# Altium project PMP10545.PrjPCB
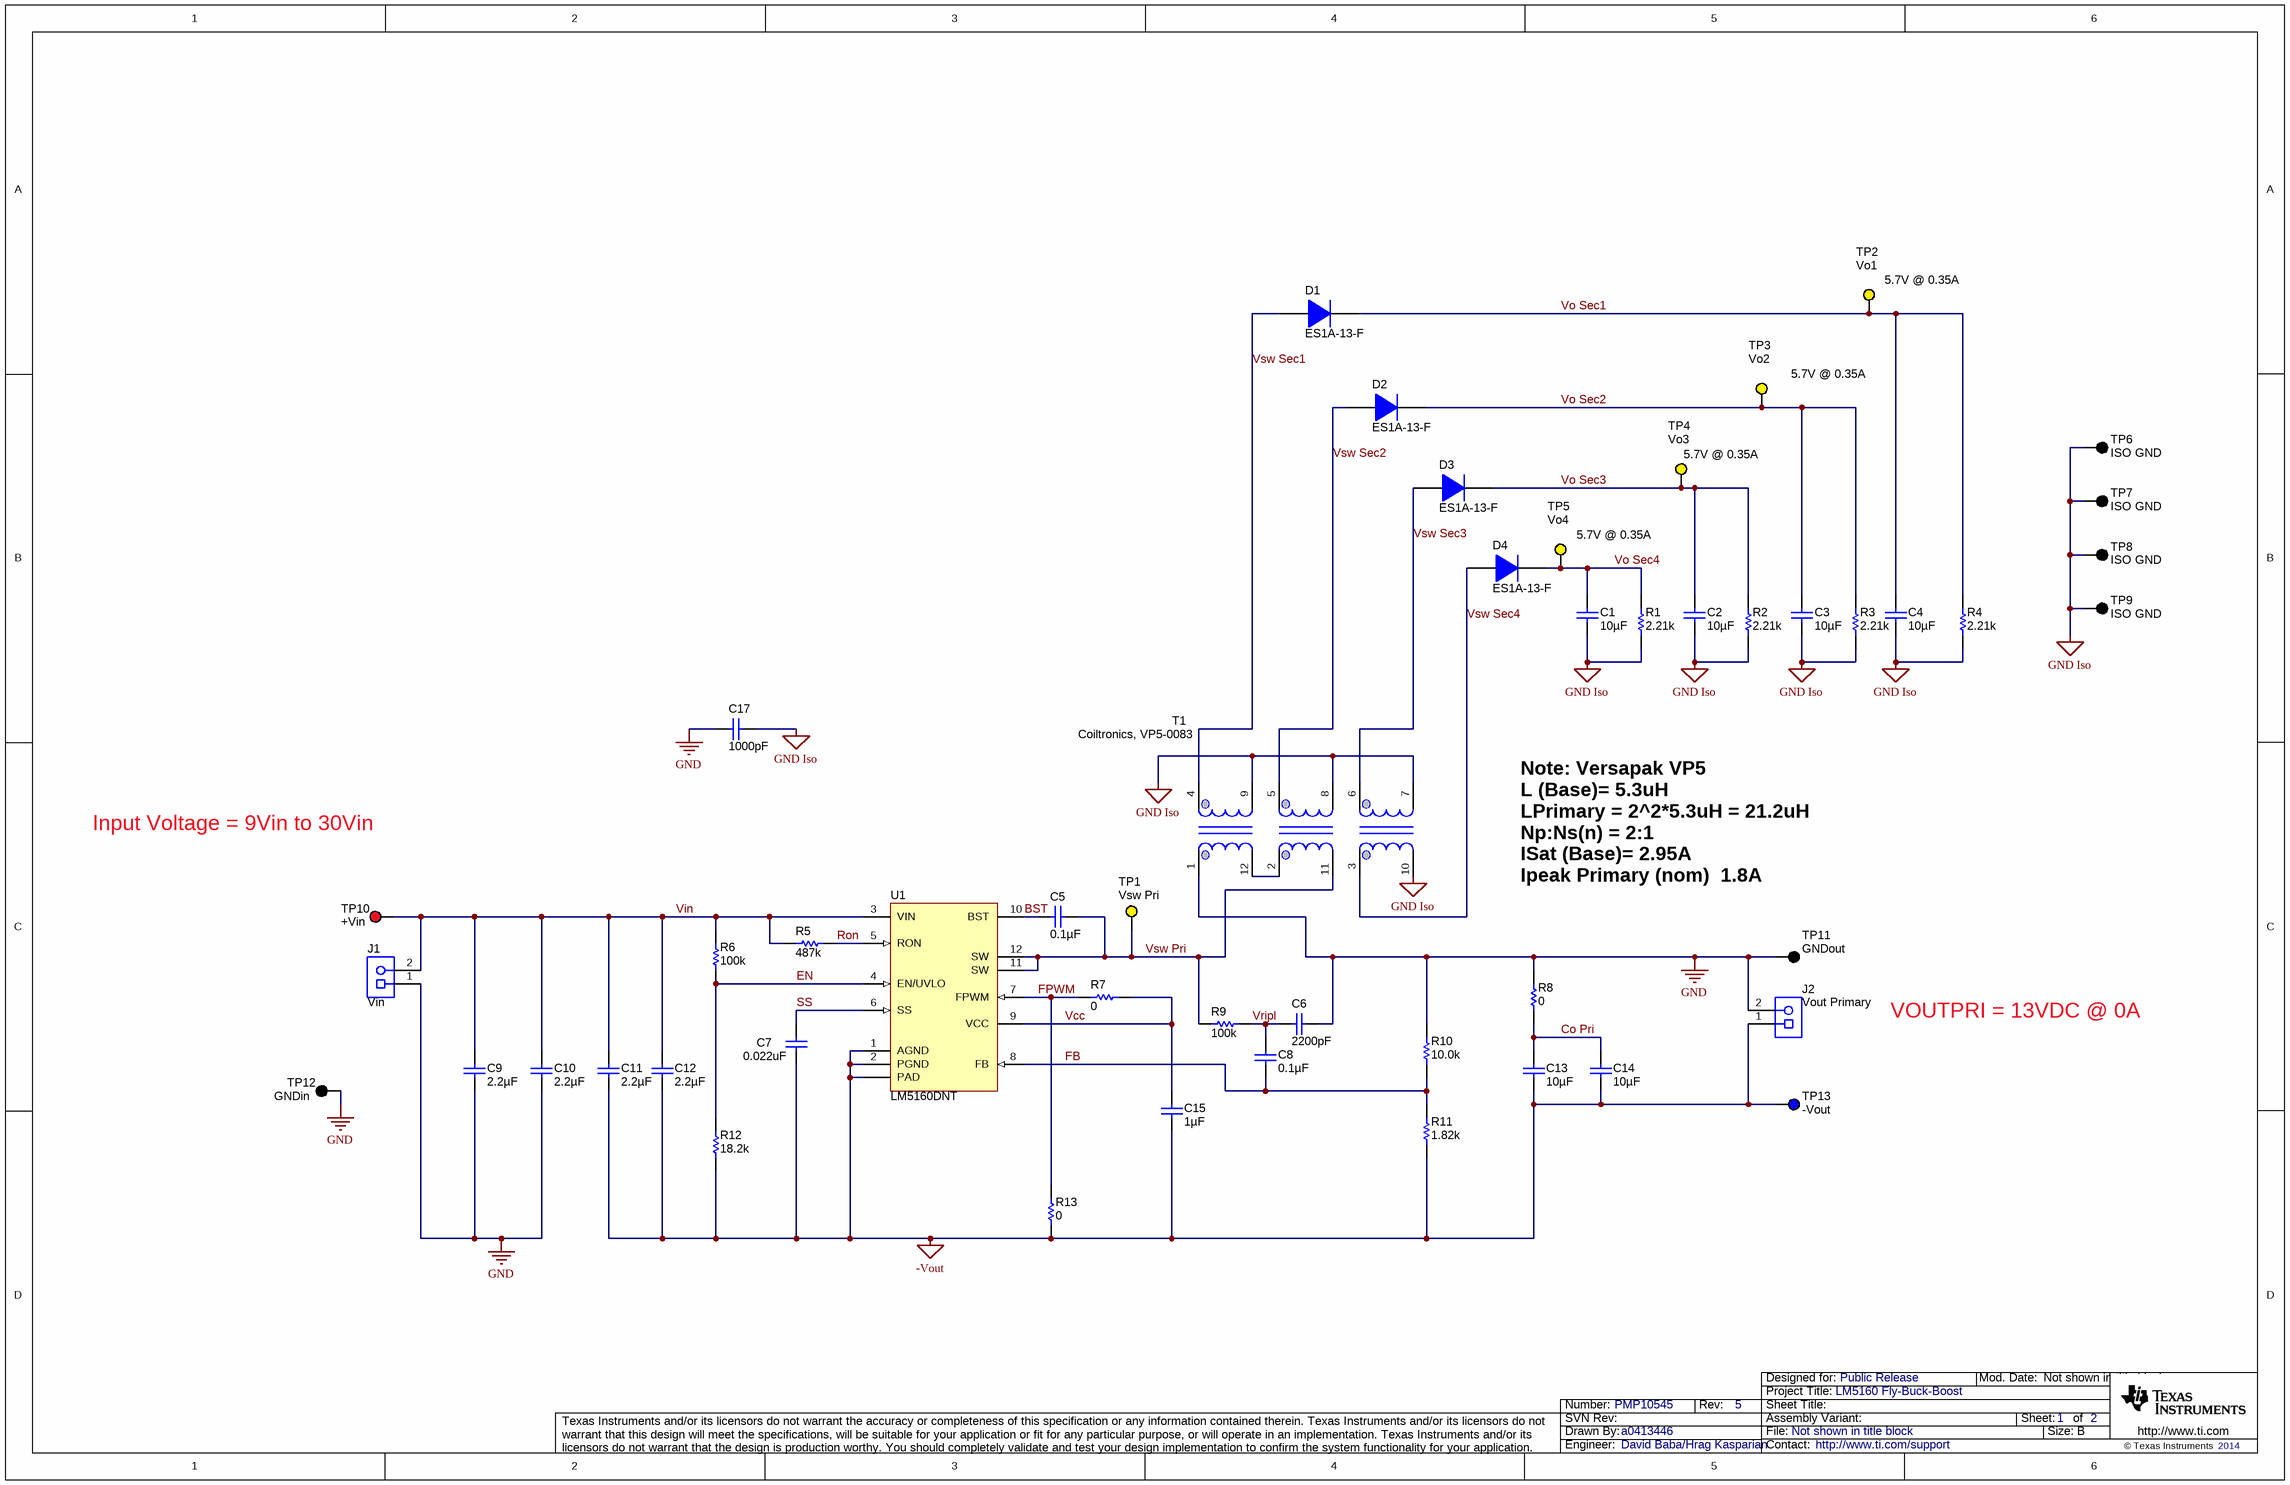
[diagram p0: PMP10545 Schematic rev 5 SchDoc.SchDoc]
TID: PMP10545; TechSupport: http://www.ti.com/support; SCH_Rev: 5; PRJ_Title: LM5160 Fly-Buck-Boost; PRJ_Number: PMP10545; PRJ_Engineer: David Baba/Hrag Kasparian; PRJ_Customer: Public Release; PCB_Layout: Hrag Kasparian; CopyrightYear: 2014
2 sheets, 63 parts. Net scope: global (net labels, ports and power ports of the same name join across sheets).
Board file: PMP10545.PcbDoc
Sheets:
  PMP10545 Schematic rev 5 SchDoc.SchDoc
  PMP10545_Hardware_ANSI-B.SchDoc

## Sheet PMP10545 Schematic rev 5 SchDoc.SchDoc
size 431 x 279 mm; Date: Not shown in title block; ApprovedBy: Not shown in title block; CheckedBy: Not shown in title block; Author: Not shown in title block; CompanyName: Not shown in title block; DrawnBy: a0413446; Engineer: Not shown in title block; Organization: Not shown in title block; Address1: Not shown in title block; Address2: Not shown in title block; Address3: Not shown in title block; Address4: Not shown in title block; DocumentNumber: 1; Revision: Use project parameter SCH_Rev; SheetNumber: 1; SheetTotal: 2; PageSetup: Record=PageOptions¦CenterHorizontal=True¦CenterVertical=True¦PrintScale=0.61¦XCorrection=1.00¦YCorrection=1.00¦PrintKind=0¦BorderSize=5000000¦LeftOffset=0¦BottomOffset=0¦Orientation=2¦PaperLength=1000¦PaperWidth=1000¦Scale=100¦PaperSource=15¦PrintQuality=600¦MediaType=1¦DitherType=10¦PaperKind=Letter¦PrintScaleMode=1

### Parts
C1  ValueDisplayed: 10µF  [0805_HV]  (hidden comment: EMK212BJ106KG-T)
C2  ValueDisplayed: 10µF  [0805_HV]  (hidden comment: EMK212BJ106KG-T)
C3  ValueDisplayed: 10µF  [0805_HV]  (hidden comment: EMK212BJ106KG-T)
C4  ValueDisplayed: 10µF  [0805_HV]  (hidden comment: EMK212BJ106KG-T)
C5  ValueDisplayed: 0.1µF  [0603]  (hidden comment: C0603C104J3RAC)
C6  ValueDisplayed: 2200pF  [0603]  (hidden comment: C0603C222K5RAC)
C7  ValueDisplayed: 0.022uF  [0603]  (hidden comment: GRM188R71C223KA01D)
C8  ValueDisplayed: 0.1µF  [0603]  (hidden comment: C0603C104J3RAC)
C9  ValueDisplayed: 2.2µF  [1206]  (hidden comment: GRM31CR61H225KA88L)
C10  ValueDisplayed: 2.2µF  [1206]  (hidden comment: GRM31CR61H225KA88L)
C11  ValueDisplayed: 2.2µF  [1206]  (hidden comment: GRM31CR61H225KA88L)
C12  ValueDisplayed: 2.2µF  [1206]  (hidden comment: GRM31CR61H225KA88L)
C13  ValueDisplayed: 10µF  [0805_HV]  (hidden comment: EMK212BJ106KG-T)
C14  ValueDisplayed: 10µF  [0805_HV]  (hidden comment: EMK212BJ106KG-T)
C15  ValueDisplayed: 1µF  [0603]  (hidden comment: GRM188R71E105KA12D)
C17  ValueDisplayed: 1000pF  [1206]  (hidden comment: VJ1206A102JXGAT5Z)
D1  ES1A-13-F  [SMA]
D2  ES1A-13-F  [SMA]
D3  ES1A-13-F  [SMA]
D4  ES1A-13-F  [SMA]
J1  Vin  [PhoenixConact_1727010]
J2  Vout Primary  [PhoenixConact_1727010]
R1  ValueDisplayed: 2.21k  [0603]  (hidden comment: CRCW06032K21FKEA)
R2  ValueDisplayed: 2.21k  [0603]  (hidden comment: CRCW06032K21FKEA)
R3  ValueDisplayed: 2.21k  [0603]  (hidden comment: CRCW06032K21FKEA)
R4  ValueDisplayed: 2.21k  [0603]  (hidden comment: CRCW06032K21FKEA)
R5  value 487k  [0603]  (hidden comment: CRCW0603487KFKEA)
R6  ValueDisplayed: 100k  [0603]  (hidden comment: CRCW0603100KFKEA)
R7  ValueDisplayed: 0  [0603]  (hidden comment: CRCW06030000Z0EA)
R8  ValueDisplayed: 0  [0805_HV]  (hidden comment: CRCW08050000Z0EA)
R9  value 100k  [0603]  (hidden comment: CRCW0603100KFKEA)
R10  value 10.0k  [0603]  (hidden comment: CRCW060310K0FKEA)
R11  ValueDisplayed: 1.82k  [0603]  (hidden comment: CRCW06031K82FKEA)
R12  value 18.2k  [0603]  (hidden comment: CRCW060318K2FKEA)
R13  ValueDisplayed: 0  [0603]  (hidden comment: CRCW06030000Z0EA)
T1  Coiltronics, VP5-0083  [VP5]
TP1  Vsw Pri  [Keystone5014]
TP2  Vo1  [Keystone5014]
TP3  Vo2  [Keystone5014]
TP4  Vo3  [Keystone5014]
TP5  Vo4  [Keystone5014]
TP6  ISO GND  [Keystone5011]
TP7  ISO GND  [Keystone5011]
TP8  ISO GND  [Keystone5011]
TP9  ISO GND  [Keystone5011]
TP10  +Vin  [Keystone5010]
TP11  GNDout  [Keystone5011]
TP12  GNDin  [Keystone5011]
TP13  -Vout  [Keystone5127]
U1  LM5160DNT  [DNT0012B]

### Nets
-Vout: C7.2 C11.2 C12.2 C13.2 C14.2 C15.2 J2.1 R11.1 R12.1 R13.1 TP13.1 U1.1(AGND) U1.2(PGND) U1.13(PAD)
GND: C6.2 C9.2 C10.2 C17.2 J1.1 J2.2 R8.2 R10.2 T1.1 TP11.1 TP12.1
GND Iso: C1.2 C2.2 C3.2 C4.2 C17.1 R1.1 R2.1 R3.1 R4.1 T1.7 T1.8 T1.9 T1.10 TP6.1 TP7.1 TP8.1 TP9.1
BST: C5.2 U1.10(BST)
Co Pri: C13.1 C14.1 R8.1
EN: R6.1 R12.2 U1.4(EN/UVLO)
FB: C8.2 R10.1 R11.2 U1.8(FB)
FPWM: R7.2 R13.2 U1.7(FPWM)
Ron: R5.1 U1.5(RON)
SS: C7.1 U1.6(SS)
Vcc: C15.1 R7.1 U1.9(VCC)
Vin: C9.1 C10.1 C11.1 C12.1 J1.2 R5.2 R6.2 TP10.1 U1.3(VIN)
Vo Sec1: C4.1 D1.1(K) R4.2 TP2.1
Vo Sec2: C3.1 D2.1(K) R3.2 TP3.1
Vo Sec3: C2.1 D3.1(K) R2.2 TP4.1
Vo Sec4: C1.1 D4.1(K) R1.2 TP5.1
Vripl: C6.1 C8.1 R9.2
Vsw Pri: C5.1 R9.1 T1.11 TP1.1 U1.11(SW) U1.12(SW)
Vsw Sec1: D1.2(A) T1.4
Vsw Sec2: D2.2(A) T1.5
Vsw Sec3: D3.2(A) T1.6
Vsw Sec4: D4.2(A) T1.3
NetT1_2: T1.2 T1.12

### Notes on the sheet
- (near TP2) 5.7V @ 0.35A
- (near TP3) 5.7V @ 0.35A
- (near TP4) 5.7V @ 0.35A
- (near TP5) 5.7V @ 0.35A
- Input Voltage = 9Vin to 30Vin
- Note: Versapak VP5
  L (Base)= 5.3uH
  LPrimary = 2^2*5.3uH = 21.2uH
  Np:Ns(n) = 2:1
  ISat (Base)= 2.95A
  Ipeak Primary (nom)  1.8A
- VOUTPRI = 13VDC @ 0A

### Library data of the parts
C1-C4 C13 C14 = EMK212BJ106KG-T: CAP, CERM, 10uF, 16V, +/-10%, X5R, 0805; Manufacturer: Taiyo Yuden; Polarized: N; CompType: Capacitor; U/M: EA; Cap_F: 0.00001; Tolerance_%: 10; Value1: Unknown; VDC_V: 16; TaMin_C: -55; TaMax_C: 85; Cap_Case: 0805
C5 C8 = C0603C104J3RAC: CAP, CERM, 0.1uF, 25V, +/-5%, X7R, 0603; Manufacturer: Kemet; Polarized: N; CompType: Capacitor; U/M: EA; Cap_F: 0.0000001; Tolerance_%: 5; Value1: Unknown; VDC_V: 25; TaMin_C: -55; TaMax_C: 125
C6 = C0603C222K5RAC: CAP, CERM, 2200pF, 50V, +/-10%, X7R, 0603; Manufacturer: Kemet; Polarized: N; CompType: Capacitor; U/M: EA; Cap_F: 0.0000000022; Tolerance_%: 10; Value1: Unknown; VDC_V: 50; TaMin_C: -55; TaMax_C: 125
C7 = GRM188R71C223KA01D: CAP, CERM, 0.022uF, 16V, +/-10%, X7R, 0603; Manufacturer: MuRata; Polarized: N; CompType: Capacitor; U/M: EA; Cap_F: 0.000000022; Tolerance_%: 10; Value1: Unknown; VDC_V: 16; TaMin_C: -55; TaMax_C: 125
C9-C12 = GRM31CR61H225KA88L: CAP, CERM, 2.2uF, 50V, +/-10%, X5R, 1206; Manufacturer: MuRata; Polarized: N; CompType: Capacitor; U/M: EA; Cap_F: 0.0000022; Tolerance_%: 10; Value1: Unknown; VDC_V: 50; TaMin_C: -55; TaMax_C: 85
C15 = GRM188R71E105KA12D: CAP, CERM, 1uF, 25V, +/-10%, X7R, 0603; Manufacturer: MuRata; Polarized: N; CompType: Capacitor; U/M: EA; Cap_F: 0.000001; Tolerance_%: 10; Value1: Unknown; VDC_V: 25; TaMin_C: -55; TaMax_C: 125
C17 = VJ1206A102JXGAT5Z: CAP, CERM, 1000pF, 1000V, +/-5%, C0G/NP0, 1206; Manufacturer: Vishay-Vitramon; Polarized: N; CompType: Capacitor; U/M: EA; Cap_F: 0.000000001; Tolerance_%: 5; Value1: Unknown; VDC_V: 1000; TaMin_C: -55; TaMax_C: 125
D1-D4 = ES1A-13-F: Diode, Ultrafast, 50V, 1A, SMA; Manufacturer: Diodes Inc.; U/M: EA; Vf_V: 0.88; Value2: 0.88V; Io_A: 1; Vr_V: 50
J1 J2 = 1727010: Conn Term Block, 2POS, 3.81mm, TH; Manufacturer: Phoenix Contact; SymbolCreator: a0412235; Value: 2x1; CompType: Terminal Block; U/M: EA
R1-R4 = CRCW06032K21FKEA: RES, 2.21 k, 1%, 0.1 W, 0603; Manufacturer: Vishay-Dale; CompType: Resistor; Value: 2.21k; Res_ohm: 2210; Value_Code: 2k21; Tolerance_%: 1; Power_W: 0.1; Value2: 0.1W; VDC_V: 75; TempCo: 100 ppm/C; EIA_Code: E96; U/M: EA
R5 = CRCW0603487KFKEA: RES, 487k ohm, 1%, 0.1W, 0603; Manufacturer: Vishay-Dale; CompType: Resistor; Res_ohm: 487000; Tolerance_%: 1; Power_W: 0.1; VDC_V: 75; TempCo: 100 ppm/C; EIA_Code: E96; U/M: EA
R6 = CRCW0603100KFKEA: RES, 100 k, 1%, 0.1 W, 0603; Manufacturer: Vishay-Dale; CompType: Resistor; Value: 100k; Res_ohm: 100000; Tolerance_%: 1; Power_W: 0.1; Value2: 0.1W; VDC_V: 75; TempCo: 100 ppm/C; EIA_Code: E96; U/M: EA
R7 R13 = CRCW06030000Z0EA: RES, 0, 5%, 0.1 W, 0603; Manufacturer: Vishay-Dale; CompType: Resistor; Value: 0; Value_Code: 0000; Tolerance_%: 5; Power_W: 0.1; Value2: 0.1W; VDC_V: 75; TempCo: 200 ppm/C; EIA_Code: E24; U/M: EA
R8 = CRCW08050000Z0EA: RES, 0, 5%, 0.125 W, 0805; Manufacturer: Vishay-Dale; CompType: Resistor; Value: 0; Value_Code: 0000; Tolerance_%: 5; Power_W: 0.125; Value2: 0.125W; VDC_V: 150; TempCo: 200 ppm/C; EIA_Code: E24; U/M: EA
R9 = CRCW0603100KFKEA: RES, 100k ohm, 1%, 0.1W, 0603; Manufacturer: Vishay-Dale; CompType: Resistor; U/M: EA; Res_ohm: 100000; Tolerance_%: 1; Power_W: 0.1; VDC_V: 75; TempCo: 100 ppm/C; EIA_Code: E96
R10 = CRCW060310K0FKEA: RES, 10.0k ohm, 1%, 0.1W, 0603; Manufacturer: Vishay-Dale; CompType: Resistor; U/M: EA; Res_ohm: 10000; Value_Code: 10k0; Tolerance_%: 1; Power_W: 0.1; VDC_V: 75; TempCo: 100 ppm/C; EIA_Code: E96
R11 = CRCW06031K82FKEA: RES, 1.82 k, 1%, 0.1 W, 0603; Manufacturer: Vishay-Dale; CompType: Resistor; Value: 1.82k; Res_ohm: 1820; Value_Code: 1k82; Tolerance_%: 1; Power_W: 0.1; Value2: 0.1W; VDC_V: 75; TempCo: 100 ppm/C; EIA_Code: E96; U/M: EA
R12 = CRCW060318K2FKEA: RES, 18.2k ohm, 1%, 0.1W, 0603; Manufacturer: Vishay-Dale; CompType: Resistor; Res_ohm: 18200; Value_Code: 18k2; Tolerance_%: 1; Power_W: 0.1; VDC_V: 75; TempCo: 100 ppm/C; EIA_Code: E96; U/M: EA
T1 = VP5XFMR: PartNumber: VP5-0083TR; Value: 190.8uH; Description: VERSA-PAC Inductor
TP1-TP5 = 5014: Test Point, Multipurpose, Yellow, TH; Manufacturer: Keystone; CompType: Test Point Loop; U/M: EA
TP6-TP9 TP11 TP12 = 5011: Test Point, Multipurpose, Black, TH; Manufacturer: Keystone; CompType: Test Point Loop; U/M: EA
TP10 = 5010: Test Point, Multipurpose, Red, TH; Manufacturer: Keystone; CompType: Test Point Loop; U/M: EA
TP13 = 5127: Test Point, Multipurpose, Blue, TH; Manufacturer: Keystone; CompType: Test Point Loop; U/M: EA
U1 = LM5160DNT: Wide Input 65V, 1.5A Synchronous Step-Down DC-DC Converter, DNT0012B; Manufacturer: Texas Instruments; Alternate Manufacturer: None; SymbolCreator: a0411947; CompType: IC; U/M: EA

## Sheet PMP10545_Hardware_ANSI-B.SchDoc
size 431 x 279 mm; Date: Not shown in title block; ApprovedBy: Not shown in title block; CheckedBy: Not shown in title block; Author: Not shown in title block; CompanyName: Not shown in title block; Engineer: Not shown in title block; Organization: Not shown in title block; Address1: Not shown in title block; Address2: Not shown in title block; Address3: Not shown in title block; Address4: Not shown in title block; DocumentNumber: 2; Revision: Use project parameter SCH_Rev; SheetNumber: 2; SheetTotal: 2; PageSetup: Record=PageOptions¦CenterHorizontal=True¦CenterVertical=True¦PrintScale=1.00¦XCorrection=1.00¦YCorrection=1.00¦PrintKind=0¦BorderSize=5000000¦LeftOffset=0¦BottomOffset=0¦Orientation=2¦PaperLength=1000¦PaperWidth=1000¦Scale=100¦PaperSource=15¦PrintQuality=600¦MediaType=1¦DitherType=10¦PaperKind=Letter¦PrintScaleMode=1
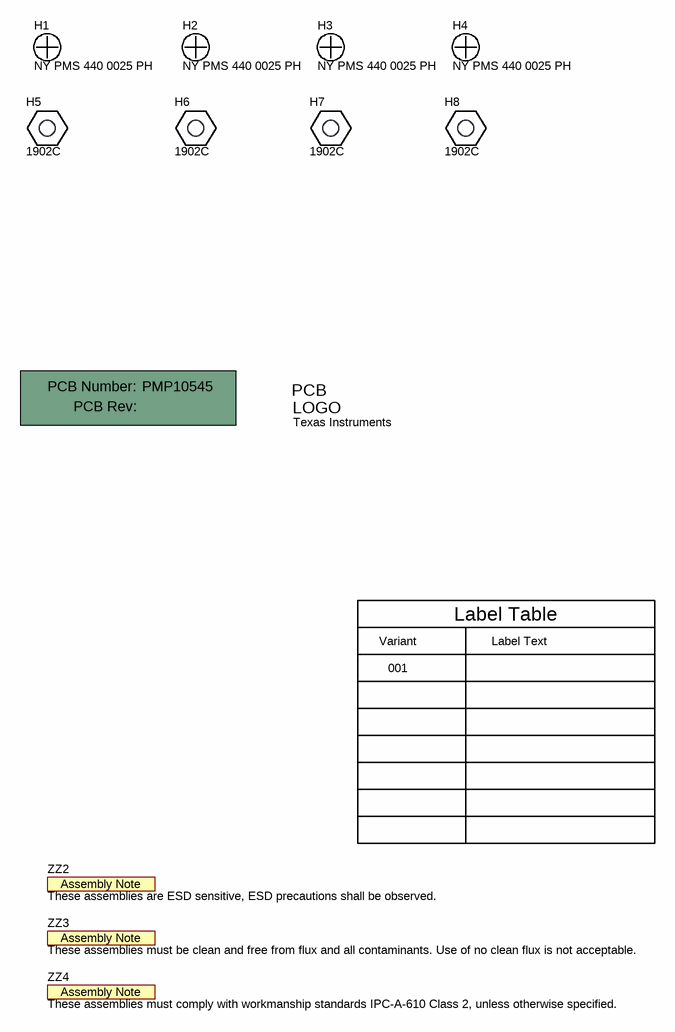
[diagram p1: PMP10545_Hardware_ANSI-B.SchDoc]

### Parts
!PCB  Printed Circuit Board  (value not drawn)  (mechanical)
H1  NY PMS 440 0025 PH  [NY PMS 440 0025 PH]
H2  NY PMS 440 0025 PH  [NY PMS 440 0025 PH]
H3  NY PMS 440 0025 PH  [NY PMS 440 0025 PH]
H4  NY PMS 440 0025 PH  [NY PMS 440 0025 PH]
H5  1902C  [Keystone_1902C]
H6  1902C  [Keystone_1902C]
H7  1902C  [Keystone_1902C]
H8  1902C  [Keystone_1902C]
Logo1  Texas Instruments  [TI_Stacked_Overlay_Medium]  (no BOM)
ZZ2  These assemblies are ESD sensitive, ESD precautions shall be observed.  [AssemblyNote]  (no BOM)
ZZ3  These assemblies must be clean and free from flux and all contaminants. Use of no clean flux is not acceptable.  [AssemblyNote]  (no BOM)
ZZ4  These assemblies must comply with workmanship standards IPC-A-610 Class 2, unless otherwise specified.  [AssemblyNote]  (no BOM)

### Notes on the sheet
- Variant
- Label Table
- Label Text
- 001

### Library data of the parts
!PCB = PCB: Manufacturer: Any; PartNumber: PMP10545; SymbolCreator: a0412235
H1-H4 = NY PMS 440 0025 PH: Machine Screw, Round, #4-40 x 1/4, Nylon, Philips panhead; Manufacturer: B&F Fastener Supply; CompType: Hardware; SymbolCreator: codlsc; U/M: EA
H5-H8 = 1902C: Standoff, Hex, 0.5"L #4-40 Nylon; Manufacturer: Keystone; CompType: Hardware; SymbolCreator: a0412235
Logo1 = TI_Logo: Texas Instrument Corporate Signature; SymbolCreator: a0412235
ZZ2-ZZ4 = AssemblyNote: SymbolCreator: codlsc

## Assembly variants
001: not fitted FID1 FID2 FID3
